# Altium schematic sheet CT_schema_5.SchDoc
size 297 x 271 mm
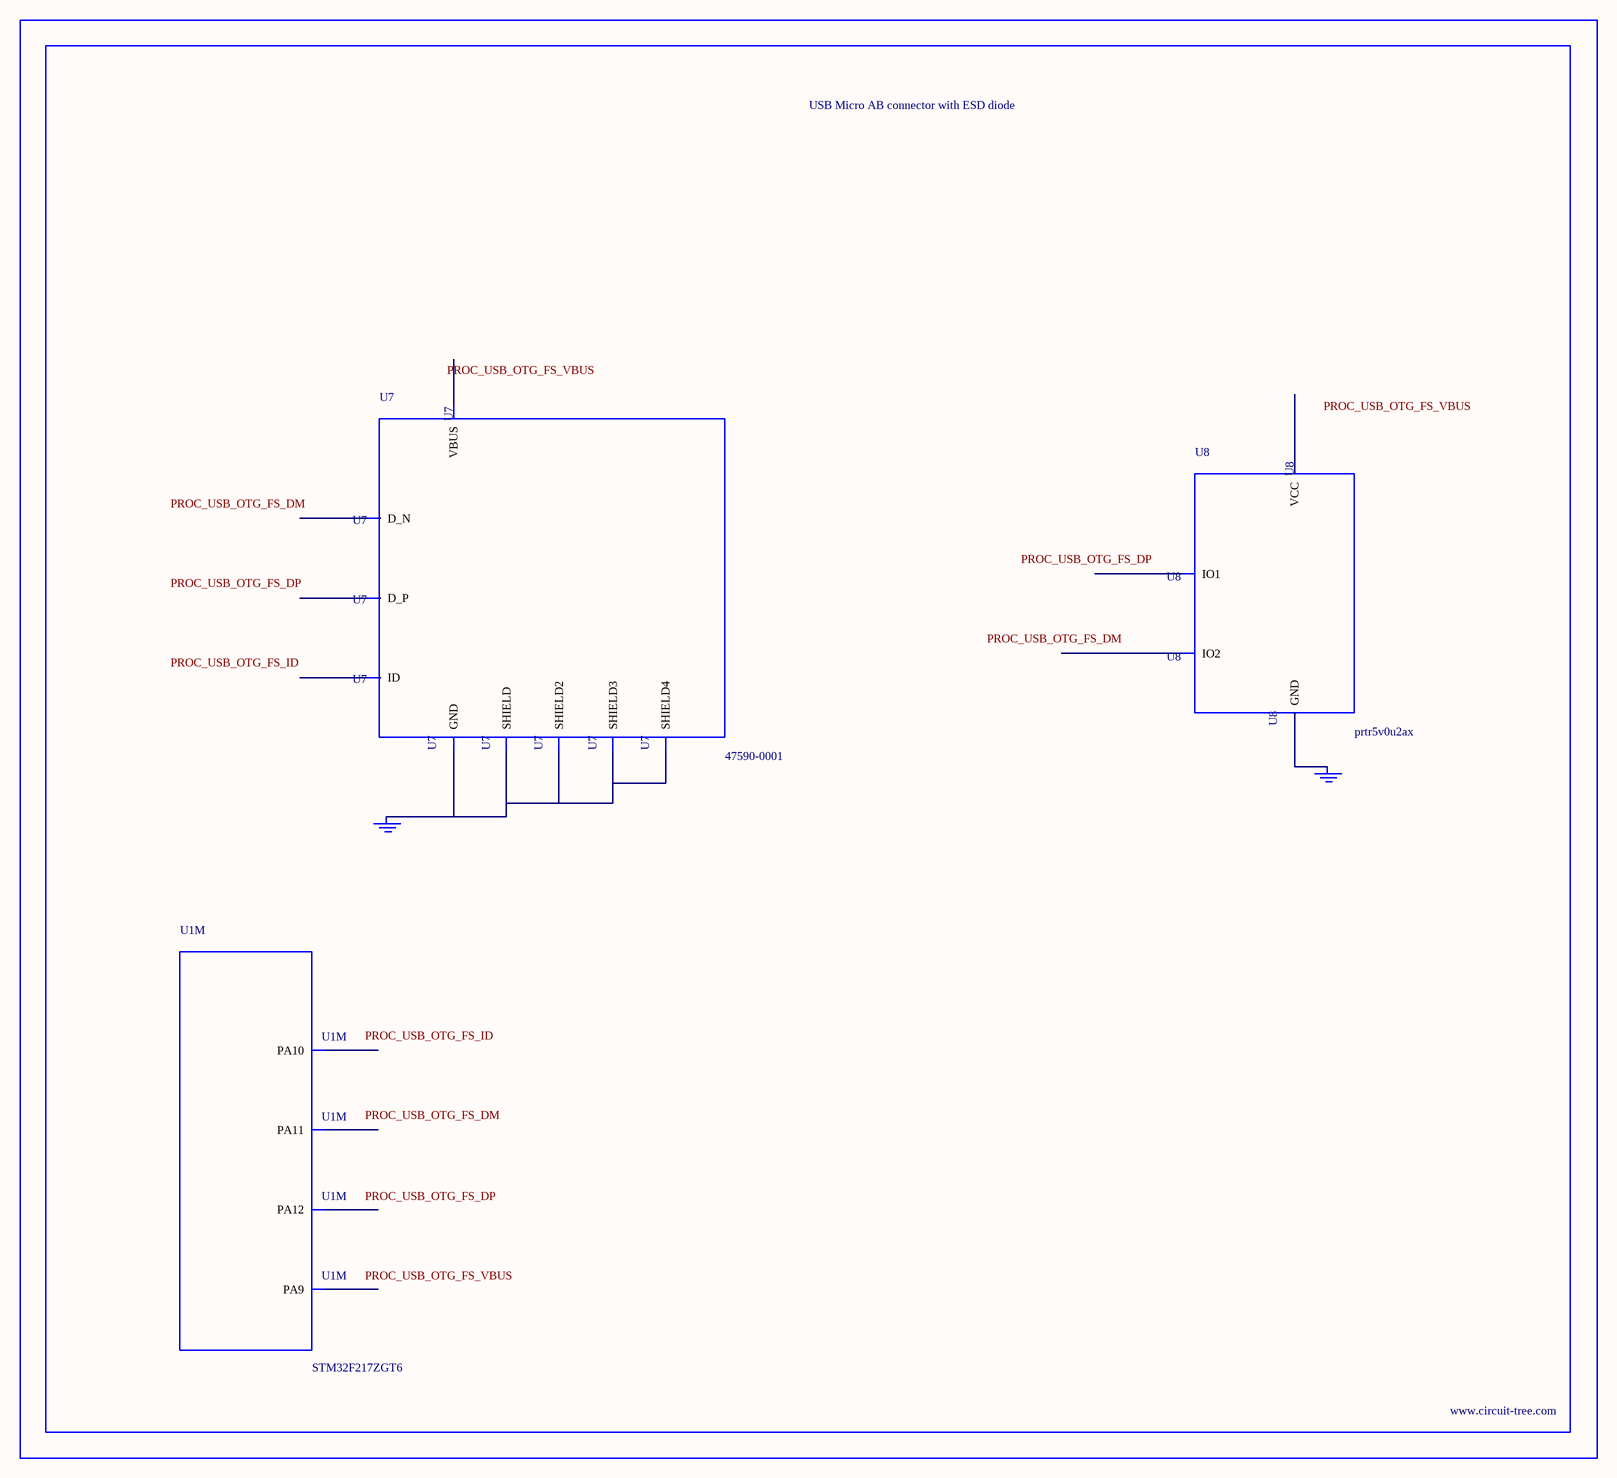
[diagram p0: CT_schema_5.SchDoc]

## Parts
BORDER4  (no value)
GND_INSTANCE_4_0  (no value)
GND_INSTANCE_4_1  (no value)
U1  STM32F217ZGT6  [LQFP144]  (part M of 13)
U7  47590-0001  [MICRO_USB_AB]
U8  prtr5v0u2ax  [SOT143B]

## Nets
NetGND_INSTANCE_4_0_0: GND_INSTANCE_4_0.0(GND) U7.5(GND) U7.6(SHIELD) U7.7(SHIELD2) U7.8(SHIELD3) U7.9(SHIELD4)
NetGND_INSTANCE_4_1_0: GND_INSTANCE_4_1.0(GND) U8.1(GND)

Not connected (* = marked no-connect by the designer): U1 101(PA9) 102(PA10) 103(PA11) 104(PA12); U7 1(VBUS) 2(D_N) 3(D_P) 4(ID); U8 2(IO1) 3(IO2) 4(VCC)

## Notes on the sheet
- Labels drawn without touching a wire or pin: PROC_USB_OTG_FS_DM, PROC_USB_OTG_FS_DP, PROC_USB_OTG_FS_ID, PROC_USB_OTG_FS_VBUS

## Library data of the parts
BORDER4 = BORDER_PAGE4
GND_INSTANCE_4_0 GND_INSTANCE_4_1 = GND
